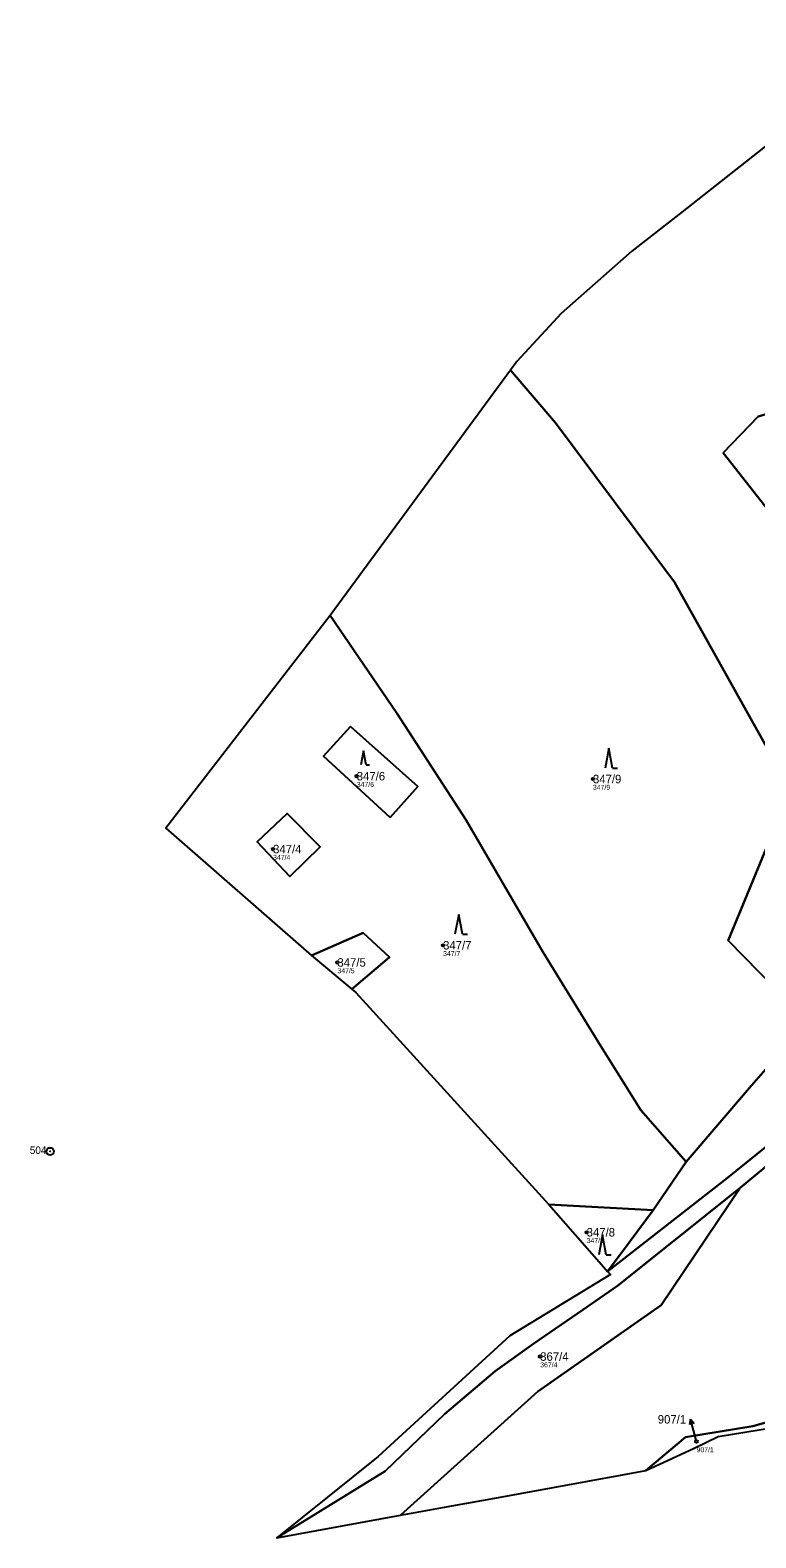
# Model space of a CAD drawing. Extents: x -734504 to -730695, y -1027923 to -1024502.
# Drawn here: x -733585.6 to -733440, y -1027006.6 to -1026704.1 of the extents above; entities that cross this region are included whole.
import ezdxf

# ---------------------------------------------------------------- set-up
doc = ezdxf.new("R2010")
doc.units = 0
for name, color, linetype in [('Definiční body', 7, 'Continuous'), ('Hranice parcel', 7, 'Continuous'), ('Parcelní čísla', 7, 'Continuous'), ('Polygon ku', 7, 'Continuous'), ('Polygon parcely', 7, 'Continuous'), ('Pop  PČ popisy', 7, 'Continuous'), ('Značky bodu BP', 7, 'Continuous'), ('Značky kultur', 7, 'Continuous')]:
    doc.layers.add(name, color=color, linetype=linetype)

msp = doc.modelspace()

# ---------------------------------------------------------------- linework, layer by layer
at = {"layer": 'Definiční body'}
for centre in [(-733520.1, -1026853.8), (-733472.72, -1026854.38), (-733536.88, -1026868.43), (-733502.78, -1026887.72), (-733523.98, -1026891.17), (-733473.98, -1026945.3), (-733483.3, -1026970.23), (-733451.94, -1026987.27)]:
    msp.add_circle(centre, 0.25, dxfattribs=at)
at = {"layer": 'Hranice parcel'}
for p, q in [((-733424.21, -1026716.46), (-733454.91, -1026740.64)), ((-733454.91, -1026740.64), (-733464.9, -1026748.5)), ((-733464.9, -1026748.5), (-733479.1, -1026761)), ((-733489.28, -1026772.35), (-733525.4, -1026821.6)), ((-733529.2, -1026889.8), (-733521.11, -1026896.53)), ((-733521.11, -1026896.53), (-733520.3, -1026897.2)), ((-733520.3, -1026897.2), (-733481.6, -1026939.7)), ((-733460.61, -1026940.86), (-733454, -1026931.16)), ((-733481.6, -1026939.7), (-733460.61, -1026940.86)), ((-733481.6, -1026939.7), (-733471.01, -1026951.74)), ((-733471.01, -1026951.74), (-733469.77, -1026953.15)), ((-733469.77, -1026953.15), (-733469.2, -1026953.8)), ((-733447.6, -1026986.3), (-733436.9, -1026984.5)), ((-733462.1, -1026993.1), (-733452.45, -1026988.58)), ((-733452.45, -1026988.58), (-733447.6, -1026986.3)), ((-733493.15, -1026998.76), (-733467.52, -1026994.09)), ((-733467.52, -1026994.09), (-733462.1, -1026993.1)), ((-733511.33, -1027002.08), (-733501.01, -1027000.2)), ((-733501.01, -1027000.2), (-733493.15, -1026998.76)), ((-733536.1, -1027006.6), (-733511.33, -1027002.08))]:
    msp.add_line(p, q, dxfattribs=at)
for points in [[(-733479.1, -1026761), (-733488, -1026770.6), (-733489.28, -1026772.35)], [(-733433.06, -1026856.55), (-733456.38, -1026814.87), (-733480.2, -1026782.9), (-733489.28, -1026772.35)], [(-733446.57, -1026788.91), (-733435.31, -1026803.3), (-733426.38, -1026799.97), (-733419.88, -1026793.39), (-733430.71, -1026779.04), (-733439.61, -1026781.63), (-733446.57, -1026788.91)], [(-733525.4, -1026821.6), (-733558.4, -1026864.2), (-733529.2, -1026889.8)], [(-733454, -1026931.16), (-733463.13, -1026920.79), (-733471.67, -1026907.08), (-733482.75, -1026889.02), (-733498.13, -1026862.61), (-733512.03, -1026841.17), (-733525.4, -1026821.6)], [(-733513.43, -1026862.07), (-733507.87, -1026855.86), (-733521.37, -1026843.85), (-733526.78, -1026849.76), (-733513.43, -1026862.07)], [(-733429.71, -1026903.01), (-733445.57, -1026886.75), (-733438.75, -1026870.28), (-733433.06, -1026856.55)], [(-733533.55, -1026873.96), (-733527.44, -1026868), (-733534.07, -1026861.26), (-733540.1, -1026866.96), (-733533.55, -1026873.96)], [(-733521.11, -1026896.53), (-733513.54, -1026890.11), (-733518.8, -1026885.25), (-733529.2, -1026889.8)], [(-733397.23, -1026890.64), (-733402.23, -1026896.5), (-733413.32, -1026909.99), (-733420.47, -1026917.19), (-733427.07, -1026923.05), (-733443.19, -1026936.4)], [(-733454, -1026931.16), (-733441.29, -1026916.35), (-733440.42, -1026915.33), (-733429.71, -1026903.01)], [(-733432.87, -1026924.04), (-733445.72, -1026934.38), (-733469.77, -1026953.15)], [(-733536.1, -1027006.6), (-733514.43, -1026993.23), (-733502.49, -1026981.81), (-733492.31, -1026973.19), (-733484.6, -1026967.62), (-733474.72, -1026960.87), (-733467.81, -1026956.07), (-733443.86, -1026936.95), (-733443.19, -1026936.4)], [(-733443.19, -1026936.4), (-733459.01, -1026959.94), (-733483.8, -1026977.27), (-733511.33, -1027002.08)], [(-733469.77, -1026953.15), (-733465.46, -1026947.37), (-733460.61, -1026940.86)], [(-733469.2, -1026953.8), (-733489.4, -1026966.1), (-733515.8, -1026990.3), (-733536.1, -1027006.6)], [(-733462.1, -1026993.1), (-733454.16, -1026986.43), (-733440.62, -1026984.22), (-733435.93, -1026982.89)]]:
    msp.add_lwpolyline(points, dxfattribs=at)
at = {"layer": 'Polygon ku'}
for points in [[(-733382.6, -1026685.7), (-733415.5, -1026709.6), (-733415.89, -1026709.91), (-733424.21, -1026716.46), (-733454.91, -1026740.64), (-733464.9, -1026748.5), (-733479.1, -1026761), (-733488, -1026770.6), (-733489.28, -1026772.35)], [(-733489.28, -1026772.35), (-733525.4, -1026821.6), (-733558.4, -1026864.2), (-733529.2, -1026889.8), (-733521.11, -1026896.53), (-733520.3, -1026897.2), (-733481.6, -1026939.7), (-733471.01, -1026951.74), (-733469.77, -1026953.15), (-733469.2, -1026953.8), (-733489.4, -1026966.1), (-733515.8, -1026990.3), (-733536.1, -1027006.6), (-733511.33, -1027002.08), (-733501.01, -1027000.2), (-733493.15, -1026998.76), (-733467.52, -1026994.09), (-733462.1, -1026993.1), (-733452.45, -1026988.58), (-733447.6, -1026986.3), (-733436.9, -1026984.5)]]:
    msp.add_lwpolyline(points, dxfattribs=at)
at = {"layer": 'Polygon parcely'}
for points in [[(-733454.91, -1026740.64), (-733464.9, -1026748.5), (-733479.1, -1026761), (-733488, -1026770.6), (-733489.28, -1026772.35), (-733480.2, -1026782.9), (-733456.38, -1026814.87), (-733433.06, -1026856.55), (-733387.41, -1026843.38), (-733372.71, -1026859.43), (-733337.42, -1026829.81), (-733357.8, -1026797.6), (-733394.37, -1026742.32), (-733415.89, -1026709.91), (-733424.21, -1026716.46)], [(-733438.75, -1026870.28), (-733433.06, -1026856.55), (-733456.38, -1026814.87), (-733480.2, -1026782.9), (-733489.28, -1026772.35), (-733525.4, -1026821.6), (-733512.03, -1026841.17), (-733498.13, -1026862.61), (-733482.75, -1026889.02), (-733471.67, -1026907.08), (-733463.13, -1026920.79), (-733454, -1026931.16), (-733441.29, -1026916.35), (-733440.42, -1026915.33), (-733429.71, -1026903.01), (-733445.57, -1026886.75)], [(-733446.57, -1026788.91), (-733435.31, -1026803.3), (-733426.38, -1026799.97), (-733419.88, -1026793.39), (-733430.71, -1026779.04), (-733439.61, -1026781.63)], [(-733446.57, -1026788.91), (-733439.61, -1026781.63), (-733430.71, -1026779.04), (-733419.88, -1026793.39), (-733426.38, -1026799.97), (-733435.31, -1026803.3)], [(-733520.3, -1026897.2), (-733481.6, -1026939.7), (-733460.61, -1026940.86), (-733454, -1026931.16), (-733463.13, -1026920.79), (-733471.67, -1026907.08), (-733482.75, -1026889.02), (-733498.13, -1026862.61), (-733512.03, -1026841.17), (-733525.4, -1026821.6), (-733558.4, -1026864.2), (-733529.2, -1026889.8), (-733518.8, -1026885.25), (-733513.54, -1026890.11), (-733521.11, -1026896.53)], [(-733513.43, -1026862.07), (-733507.87, -1026855.86), (-733521.37, -1026843.85), (-733526.78, -1026849.76)], [(-733513.43, -1026862.07), (-733526.78, -1026849.76), (-733521.37, -1026843.85), (-733507.87, -1026855.86)], [(-733426.08, -1026867.75), (-733428.67, -1026863.6), (-733433.06, -1026856.55), (-733438.75, -1026870.28), (-733445.57, -1026886.75), (-733429.71, -1026903.01), (-733412.72, -1026886.33)], [(-733533.55, -1026873.96), (-733527.44, -1026868), (-733534.07, -1026861.26), (-733540.1, -1026866.96)], [(-733533.55, -1026873.96), (-733540.1, -1026866.96), (-733534.07, -1026861.26), (-733527.44, -1026868)], [(-733529.2, -1026889.8), (-733521.11, -1026896.53), (-733513.54, -1026890.11), (-733518.8, -1026885.25)], [(-733536.1, -1027006.6), (-733511.33, -1027002.08), (-733483.8, -1026977.27), (-733459.01, -1026959.94), (-733443.19, -1026936.4), (-733443.86, -1026936.95), (-733467.81, -1026956.07), (-733474.72, -1026960.87), (-733484.6, -1026967.62), (-733492.31, -1026973.19), (-733502.49, -1026981.81), (-733514.43, -1026993.23)], [(-733481.6, -1026939.7), (-733471.01, -1026951.74), (-733469.77, -1026953.15), (-733465.46, -1026947.37), (-733460.61, -1026940.86)], [(-733435.93, -1026982.89), (-733440.62, -1026984.22), (-733454.16, -1026986.43), (-733462.1, -1026993.1), (-733452.45, -1026988.58), (-733447.6, -1026986.3), (-733436.9, -1026984.5)]]:
    msp.add_lwpolyline(points, close=True, dxfattribs=at)
for points in [[(-733429.71, -1026903.01), (-733440.42, -1026915.33), (-733441.29, -1026916.35), (-733454, -1026931.16), (-733460.61, -1026940.86), (-733465.46, -1026947.37), (-733469.77, -1026953.15), (-733445.72, -1026934.38), (-733432.87, -1026924.04)], [(-733432.87, -1026924.04), (-733445.72, -1026934.38), (-733469.77, -1026953.15), (-733469.2, -1026953.8), (-733489.4, -1026966.1), (-733515.8, -1026990.3), (-733536.1, -1027006.6), (-733514.43, -1026993.23), (-733502.49, -1026981.81), (-733492.31, -1026973.19), (-733484.6, -1026967.62), (-733474.72, -1026960.87), (-733467.81, -1026956.07), (-733443.86, -1026936.95), (-733443.19, -1026936.4), (-733427.07, -1026923.05)], [(-733427.07, -1026923.05), (-733443.19, -1026936.4), (-733459.01, -1026959.94), (-733483.8, -1026977.27), (-733511.33, -1027002.08), (-733501.01, -1027000.2), (-733493.15, -1026998.76), (-733467.52, -1026994.09), (-733462.1, -1026993.1), (-733454.16, -1026986.43), (-733440.62, -1026984.22), (-733435.93, -1026982.89)]]:
    msp.add_lwpolyline(points, dxfattribs=at)
at = {"layer": 'Pop  PČ popisy'}
for p, q in [((-733453.15, -1026982.81), (-733453.37, -1026983.91)), ((-733452.37, -1026985.71), (-733453.15, -1026982.81)), ((-733453.15, -1026982.81), (-733452.4, -1026983.65)), ((-733451.94, -1026987.27), (-733452.37, -1026985.71))]:
    msp.add_line(p, q, dxfattribs=at)
at = {"layer": 'Značky bodu BP'}
for radius in [0.75, 0.03]:
    msp.add_circle((-733581.59, -1026929.08), radius, dxfattribs=at)
at = {"layer": 'Značky kultur'}
for p, q in [((-733518.76, -1026848.72), (-733519.29, -1026851.52)), ((-733518.23, -1026851.52), (-733518.76, -1026848.72)), ((-733469.55, -1026848.18), (-733470.3, -1026852.18)), ((-733468.8, -1026852.18), (-733469.55, -1026848.18)), ((-733518.23, -1026851.52), (-733517.54, -1026851.52)), ((-733468.8, -1026852.18), (-733467.8, -1026852.18)), ((-733499.65, -1026881.52), (-733500.4, -1026885.52)), ((-733498.9, -1026885.52), (-733499.65, -1026881.52)), ((-733498.9, -1026885.52), (-733497.9, -1026885.52)), ((-733470.79, -1026945.8), (-733471.54, -1026949.8)), ((-733470.04, -1026949.8), (-733470.79, -1026945.8)), ((-733470.04, -1026949.8), (-733469.04, -1026949.8))]:
    msp.add_line(p, q, dxfattribs=at)

# ---------------------------------------------------------------- texts
at = {"layer": 'Definiční body'}
for s, p in [('347/6', (-733520.1, -1026855.96)), ('347/9', (-733472.72, -1026856.54)), ('347/4', (-733536.88, -1026870.59)), ('347/7', (-733502.78, -1026889.88)), ('347/5', (-733523.98, -1026893.33)), ('347/8', (-733473.98, -1026947.46)), ('367/4', (-733483.3, -1026972.39)), ('907/1', (-733451.94, -1026989.43))]:
    msp.add_text(s, height=1, dxfattribs=at).set_placement(p)
at = {"layer": 'Parcelní čísla'}
for s, p in [('347/6', (-733520.1, -1026854.65)), ('347/9', (-733472.72, -1026855.23)), ('347/4', (-733536.88, -1026869.28)), ('347/7', (-733502.78, -1026888.57)), ('347/5', (-733523.98, -1026892.02)), ('347/8', (-733473.98, -1026946.15)), ('367/4', (-733483.3, -1026971.08)), ('907/1', (-733459.72, -1026983.67))]:
    msp.add_text(s, height=1.7, dxfattribs=at).set_placement(p)
at = {"layer": 'Značky bodu BP'}
msp.add_text('504', height=1.5, dxfattribs=at).set_placement((-733585.69, -1026929.58))

doc.saveas('drawing.dxf')
